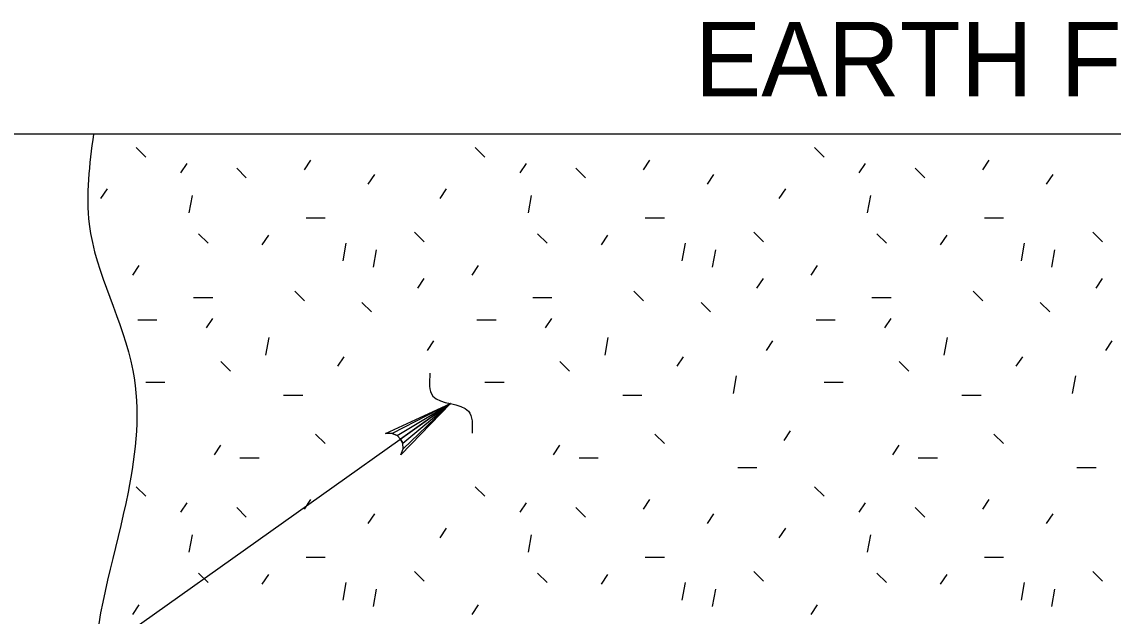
# Model space of a CAD drawing. Extents: x 1.32 to 7.47, y -3.56 to 5.14.
# Drawn here: x 3.032 to 3.909, y 0.497 to 0.974 of the extents above; entities that cross this region are included whole.
import ezdxf

# ---------------------------------------------------------------- set-up
doc = ezdxf.new("R2010")
doc.units = 0
for name, color, linetype in [('DETL-DIMS', 7, 'Continuous'), ('DETL-LINE', 7, 'Continuous'), ('DETL-NOTE', 7, 'Continuous'), ('DETL-PATT', 7, 'Continuous')]:
    doc.layers.add(name, color=color, linetype=linetype)

msp = doc.modelspace()

# ---------------------------------------------------------------- linework, layer by layer
at = {"layer": 'DETL-DIMS'}
msp.add_line((2.73853, 0.21485), (3.37668, 0.66758), dxfattribs=at)
msp.add_lwpolyline([(3.37668, 0.66758), (3.33673, 0.62625), (3.33854, 0.63123), (3.33818, 0.63562), (3.33652, 0.63908), (3.33379, 0.6418), (3.32977, 0.64359), (3.32448, 0.64353), (3.37668, 0.66758), (3.32977, 0.64359), (3.33379, 0.6418), (3.37668, 0.66758), (3.33652, 0.63908), (3.33818, 0.63562), (3.37668, 0.66758), (3.33854, 0.63123)], dxfattribs=at)
msp.add_spline([(3.36009, 0.69202), (3.36242, 0.67361), (3.39109, 0.66147), (3.39403, 0.64379)], degree=3, dxfattribs=at)
at = {"layer": 'DETL-LINE'}
msp.add_line((5.06784, 0.88409), (2.38123, 0.88409), dxfattribs=at)
msp.add_spline([(3.08952, 0.88409), (3.08605, 0.81181), (3.12129, 0.69425), (3.11738, 0.59628), (3.08996, 0.4552), (3.09388, 0.35723), (3.08213, 0.24359), (3.08605, 0.06332), (3.11346, -0.01897), (3.10563, -0.10127), (3.08213, -0.18748), (3.10563, -0.29329), (3.09388, -0.41085), (3.11738, -0.49315), (3.13304, -0.57544), (3.13304, -0.66165), (3.11738, -0.73611), (3.13696, -0.78706), (3.14088, -0.80273), (3.13696, -0.88503), (3.11982, -0.93409)], degree=3, dxfattribs=at)
at = {"layer": 'DETL-PATT'}
for p, q in [((3.12385, 0.87345), (3.13155, 0.86574)), ((3.39658, 0.87345), (3.40428, 0.86574)), ((3.6693, 0.87345), (3.67701, 0.86574)), ((3.15982, 0.8529), (3.16495, 0.86062)), ((3.25916, 0.85547), (3.26429, 0.86319)), ((3.43254, 0.8529), (3.43768, 0.86062)), ((3.53188, 0.85547), (3.53702, 0.86319)), ((3.70527, 0.8529), (3.71041, 0.86062)), ((3.80461, 0.85547), (3.80975, 0.86319)), ((3.20476, 0.85676), (3.21246, 0.84905)), ((3.31053, 0.84391), (3.31567, 0.85163)), ((3.47749, 0.85676), (3.48519, 0.84905)), ((3.58326, 0.84391), (3.5884, 0.85163)), ((3.75021, 0.85676), (3.75792, 0.84905)), ((3.85599, 0.84391), (3.86112, 0.85163)), ((3.0956, 0.83236), (3.10074, 0.84007)), ((3.1688, 0.83493), (3.16624, 0.8208)), ((3.36833, 0.83236), (3.37346, 0.84007)), ((3.44153, 0.83493), (3.43896, 0.8208)), ((3.64105, 0.83236), (3.64619, 0.84007)), ((3.71426, 0.83493), (3.71169, 0.8208)), ((3.26045, 0.81695), (3.27586, 0.81695)), ((3.53318, 0.81695), (3.54859, 0.81695)), ((3.80591, 0.81695), (3.82132, 0.81695)), ((3.17394, 0.8041), (3.18165, 0.79639)), ((3.22532, 0.79511), (3.23045, 0.80282)), ((3.34778, 0.80538), (3.35549, 0.79768)), ((3.44667, 0.8041), (3.45437, 0.79639)), ((3.49804, 0.79511), (3.50318, 0.80282)), ((3.62051, 0.80538), (3.62821, 0.79768)), ((3.7194, 0.8041), (3.7271, 0.79639)), ((3.77077, 0.79511), (3.77591, 0.80282)), ((3.89324, 0.80538), (3.90094, 0.79768)), ((3.29255, 0.79639), (3.28999, 0.78227)), ((3.31695, 0.79126), (3.31438, 0.77713)), ((3.56528, 0.79639), (3.56271, 0.78227)), ((3.58968, 0.79126), (3.58711, 0.77713)), ((3.83801, 0.79639), (3.83544, 0.78227)), ((3.86241, 0.79126), (3.85984, 0.77713)), ((3.12128, 0.77071), (3.12642, 0.77843)), ((3.39401, 0.77071), (3.39915, 0.77843)), ((3.66674, 0.77071), (3.67187, 0.77843)), ((3.35035, 0.76044), (3.35549, 0.76815)), ((3.62308, 0.76044), (3.62821, 0.76815)), ((3.8958, 0.76044), (3.90094, 0.76815)), ((3.25145, 0.75787), (3.25916, 0.75016)), ((3.52418, 0.75787), (3.53188, 0.75016)), ((3.79691, 0.75787), (3.80461, 0.75016)), ((3.17009, 0.75273), (3.1855, 0.75273)), ((3.3054, 0.74888), (3.3131, 0.74118)), ((3.44282, 0.75273), (3.45822, 0.75273)), ((3.57812, 0.74888), (3.58583, 0.74118)), ((3.71554, 0.75273), (3.73095, 0.75273)), ((3.85085, 0.74888), (3.85855, 0.74118)), ((3.12513, 0.73476), (3.14054, 0.73476)), ((3.18036, 0.72832), (3.1855, 0.73604)), ((3.39786, 0.73476), (3.41327, 0.73476)), ((3.45309, 0.72832), (3.45822, 0.73604)), ((3.67059, 0.73476), (3.686, 0.73476)), ((3.72582, 0.72832), (3.73095, 0.73604)), ((3.23045, 0.72062), (3.22788, 0.70649)), ((3.50318, 0.72062), (3.50061, 0.70649)), ((3.77591, 0.72062), (3.77334, 0.70649)), ((3.35805, 0.71035), (3.36319, 0.71806)), ((3.63078, 0.71035), (3.63592, 0.71806)), ((3.90351, 0.71035), (3.90865, 0.71806)), ((3.28613, 0.69751), (3.29127, 0.70522)), ((3.55886, 0.69751), (3.564, 0.70522)), ((3.83159, 0.69751), (3.83672, 0.70522)), ((3.19193, 0.70136), (3.19963, 0.69365)), ((3.46466, 0.70136), (3.47236, 0.69365)), ((3.73738, 0.70136), (3.74509, 0.69365)), ((3.13155, 0.68466), (3.14696, 0.68466)), ((3.40428, 0.68466), (3.41969, 0.68466)), ((3.60637, 0.6898), (3.6038, 0.67568)), ((3.67701, 0.68466), (3.69242, 0.68466)), ((3.8791, 0.6898), (3.87653, 0.67568)), ((3.24246, 0.67439), (3.25787, 0.67439)), ((3.51519, 0.67439), (3.5306, 0.67439)), ((3.78792, 0.67439), (3.80333, 0.67439)), ((3.26816, 0.64311), (3.27586, 0.6354)), ((3.54088, 0.64311), (3.54859, 0.6354)), ((3.64491, 0.63797), (3.65004, 0.64569)), ((3.81361, 0.64311), (3.82132, 0.6354)), ((3.18678, 0.62641), (3.19192, 0.63413)), ((3.45951, 0.62641), (3.46465, 0.63413)), ((3.73224, 0.62641), (3.73737, 0.63413)), ((3.20733, 0.62385), (3.22274, 0.62385)), ((3.48005, 0.62385), (3.49546, 0.62385)), ((3.75278, 0.62385), (3.76819, 0.62385)), ((3.60767, 0.61614), (3.62308, 0.61614)), ((3.8804, 0.61614), (3.8958, 0.61614)), ((3.12385, 0.60072), (3.13155, 0.59302)), ((3.39658, 0.60072), (3.40428, 0.59302)), ((3.6693, 0.60072), (3.67701, 0.59302)), ((3.25916, 0.58274), (3.26429, 0.59046)), ((3.53188, 0.58274), (3.53702, 0.59046)), ((3.80461, 0.58274), (3.80975, 0.59046)), ((3.15982, 0.58018), (3.16495, 0.58789)), ((3.20476, 0.58403), (3.21246, 0.57632)), ((3.43254, 0.58018), (3.43768, 0.58789)), ((3.47749, 0.58403), (3.48519, 0.57632)), ((3.70527, 0.58018), (3.71041, 0.58789)), ((3.75021, 0.58403), (3.75792, 0.57632)), ((3.31053, 0.57119), (3.31567, 0.5789)), ((3.58326, 0.57119), (3.5884, 0.5789)), ((3.85599, 0.57119), (3.86112, 0.5789)), ((3.1688, 0.5622), (3.16624, 0.54807)), ((3.36833, 0.55963), (3.37346, 0.56735)), ((3.44153, 0.5622), (3.43896, 0.54807)), ((3.64105, 0.55963), (3.64619, 0.56735)), ((3.71426, 0.5622), (3.71169, 0.54807)), ((3.26045, 0.54422), (3.27586, 0.54422)), ((3.53318, 0.54422), (3.54859, 0.54422)), ((3.80591, 0.54422), (3.82132, 0.54422)), ((3.17394, 0.53137), (3.18165, 0.52366)), ((3.22532, 0.52238), (3.23045, 0.5301)), ((3.34778, 0.53265), (3.35549, 0.52495)), ((3.44667, 0.53137), (3.45437, 0.52366)), ((3.49804, 0.52238), (3.50318, 0.5301)), ((3.62051, 0.53265), (3.62821, 0.52495)), ((3.7194, 0.53137), (3.7271, 0.52366)), ((3.77077, 0.52238), (3.77591, 0.5301)), ((3.89324, 0.53265), (3.90094, 0.52495)), ((3.29255, 0.52366), (3.28999, 0.50954)), ((3.31695, 0.51853), (3.31438, 0.5044)), ((3.56528, 0.52366), (3.56271, 0.50954)), ((3.58968, 0.51853), (3.58711, 0.5044)), ((3.83801, 0.52366), (3.83544, 0.50954)), ((3.86241, 0.51853), (3.85984, 0.5044)), ((3.12128, 0.49798), (3.12642, 0.5057)), ((3.39401, 0.49798), (3.39915, 0.5057)), ((3.66674, 0.49798), (3.67187, 0.5057))]:
    msp.add_line(p, q, dxfattribs=at)

# ---------------------------------------------------------------- texts
at = {"layer": 'DETL-NOTE'}
msp.add_text('EARTH FILL', height=0.06, dxfattribs=at).set_placement((3.57297, 0.9144))

doc.saveas('drawing.dxf')
